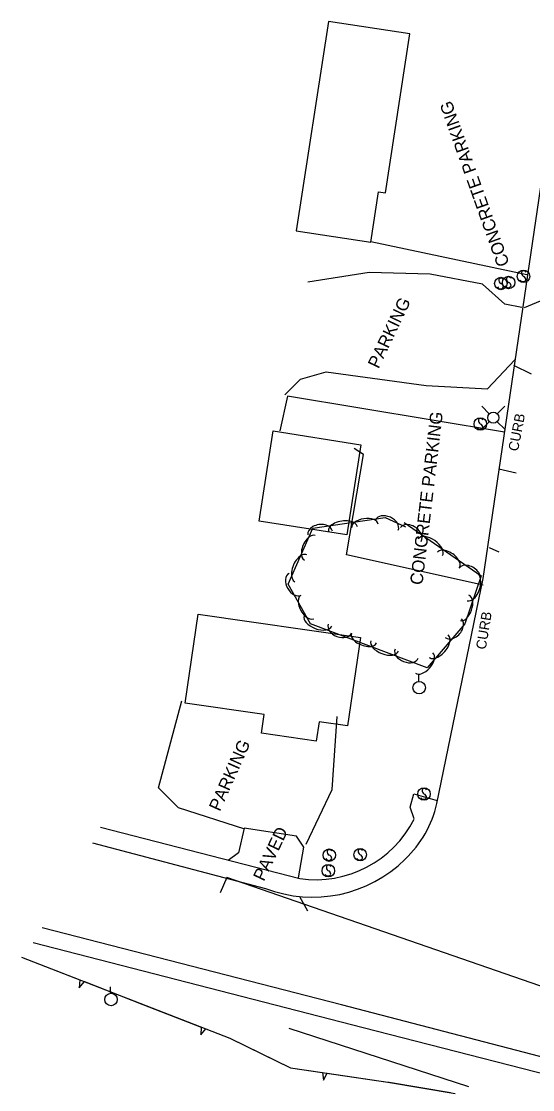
# Model space of a CAD drawing. Extents: x 978516 to 993312, y 1836504 to 1846212.
# Drawn here: x 980035.5 to 980239.3, y 1842344.4 to 1842770.2 of the extents above; entities that cross this region are included whole.
import ezdxf

# ---------------------------------------------------------------- set-up
doc = ezdxf.new("R2010")
doc.units = 0
for name, color, linetype in [('S_BUILDING', 7, 'Continuous'), ('S_CURB', 7, 'Continuous'), ('S_CURB_ANNOT', 7, 'Continuous'), ('S_EDGE_PAVEMENT', 7, 'Continuous'), ('S_PARKING', 7, 'Continuous'), ('S_PARKING_ANNOT', 7, 'Continuous'), ('S_SIDEWALK', 7, 'Continuous'), ('S_SIGN', 7, 'Continuous'), ('S_STREAM', 7, 'Continuous'), ('S_TREE', 7, 'Continuous'), ('S_UTILITY_POLE', 7, 'Continuous')]:
    doc.layers.add(name, color=color, linetype=linetype)

msp = doc.modelspace()

# ---------------------------------------------------------------- linework, layer by layer
at = {"layer": 'S_BUILDING'}
for points in [[(980157.9, 1842770.23), (980145.1, 1842686.75), (980174.82, 1842682.19), (980177.9, 1842702.26), (980180.61, 1842701.85), (980190.33, 1842765.26)], [(980130.27, 1842571.05), (980135.91, 1842606.96), (980170.84, 1842601.47), (980165.19, 1842565.57)], [(980105.96, 1842533.92), (980170.64, 1842524.55), (980165.53, 1842489.34), (980154.17, 1842490.99), (980153.05, 1842483.26), (980131.18, 1842486.43), (980132.26, 1842493.89), (980100.81, 1842498.45)]]:
    msp.add_lwpolyline(points, close=True, dxfattribs=at)
at = {"layer": 'S_CURB'}
for points in [[(980236.03, 1842656.21), (980242.46, 1842658.84)], [(980231.73, 1842633.13), (980238.8, 1842629.75)], [(980225.8, 1842591.86), (980232.71, 1842590.21)], [(980221.96, 1842560.49), (980225.89, 1842558.8)], [(980451.78, 1842317.97), (980454.14, 1842322.92), (980406.74, 1842323.37), (980408.92, 1842328.13), (980117.46, 1842428.99), (980114.74, 1842422.8)], [(980146.34, 1842421.39), (980149.6, 1842415.68)]]:
    msp.add_lwpolyline(points, dxfattribs=at)
at = {"layer": 'S_EDGE_PAVEMENT'}
for points in [[(980201.17, 1842458.38), (980219.61, 1842548.19), (980247.02, 1842734.04)], [(980063.86, 1842442.82), (980132.8, 1842424.58)], [(980258.08, 1842353.43), (980163.15, 1842378.14), (980043.71, 1842408.83)]]:
    msp.add_lwpolyline(points, dxfattribs=at)
for centre, major_axis, ratio, start_param, end_param in [((980300.02, 1842452.04), (20.47, -53.98), 0.993262, 4.118369, 5.635545), ((980158.21, 1842468.18), (43.05, -9.37), 0.999483, 5.686714, 6.273325), ((980151.52, 1842473.83), (35.98, -38.6), 0.998092, 5.16884, 6.311252)]:
    msp.add_ellipse(centre, major_axis=major_axis, ratio=ratio, start_param=start_param, end_param=end_param, dxfattribs=at)
at = {"layer": 'S_PARKING'}
for points in [[(980237.07, 1842669.22), (980174.81, 1842682.4)], [(980235.09, 1842656.2), (980228.25, 1842657.51), (980219.34, 1842665.45), (980198.52, 1842669.42), (980174.14, 1842670.14), (980149.75, 1842666.22)], [(980140.57, 1842621.38), (980146.74, 1842627.61), (980156.96, 1842630.52), (980196.85, 1842625.09), (980221.38, 1842623.76), (980232.2, 1842635.35)], [(980228.12, 1842606.46), (980141.56, 1842620.77), (980138.53, 1842606.97)], [(980219.56, 1842545.42), (980165.11, 1842557.6), (980171.84, 1842597.6), (980168.21, 1842600.02)], [(980124.58, 1842448.2), (980098.08, 1842456.66), (980090.14, 1842464.64), (980099.44, 1842499.37)], [(980148.97, 1842442.27), (980159.36, 1842464.07), (980161.42, 1842493.15)], [(980145.92, 1842428.84), (980148.06, 1842440.97), (980145.14, 1842445.44), (980124.27, 1842448.67), (980122.01, 1842438.83), (980117.91, 1842435.75)]]:
    msp.add_lwpolyline(points, dxfattribs=at)
at = {"layer": 'S_SIDEWALK'}
for points in [[(980192.11, 1842452.26), (980190.52, 1842457.02), (980192.03, 1842462.29), (980201.21, 1842459.58)], [(980066.97, 1842449.01), (980146.52, 1842428.48)], [(980040.13, 1842403.02), (980171.77, 1842369.1), (980272.43, 1842343.3), (980306.44, 1842334.58)]]:
    msp.add_lwpolyline(points, dxfattribs=at)
msp.add_ellipse((980152.58, 1842472.25), major_axis=(38.39, -22.11), ratio=0.997054, start_param=5.096353, end_param=6.337566, dxfattribs=at)
at = {"layer": 'S_SIGN'}
for centre in [(980235.67, 1842668.57), (980226.67, 1842665.71), (980229.75, 1842666.15), (980218.51, 1842609.7), (980196.05, 1842462.2), (980158.24, 1842437.85), (980170.55, 1842438.01), (980157.88, 1842431.64)]:
    msp.add_circle(centre, 2.49, dxfattribs=at)
for centre, radius, start, end in [((980236.35, 1842669.9), 1.5, 167.1196, 241.9813), ((980235.74, 1842669.84), 0.95, 16.5258, 156.8957), ((980227.36, 1842667.03), 1.5, 167.1196, 241.9813), ((980226.75, 1842666.97), 0.95, 16.5258, 156.8957), ((980226.26, 1842664.36), 1.4, 358.6529, 73.7063), ((980229.6, 1842665.32), 1.28, 204.641, 335.359), ((980230.44, 1842667.47), 1.5, 167.1196, 241.9813), ((980229.83, 1842667.41), 0.95, 16.5258, 156.8957), ((980229.34, 1842664.8), 1.4, 358.6529, 73.7063), ((980235.51, 1842667.75), 1.28, 204.641, 335.359), ((980235.25, 1842667.23), 1.4, 358.6529, 73.7063), ((980226.52, 1842664.88), 1.28, 204.641, 335.359), ((980219.19, 1842611.03), 1.5, 167.1196, 241.9813), ((980218.58, 1842610.97), 0.95, 16.5258, 156.8957), ((980218.09, 1842608.36), 1.4, 358.6529, 73.7063), ((980218.35, 1842608.88), 1.28, 204.641, 335.359), ((980196.13, 1842463.47), 0.95, 16.5258, 156.8957), ((980195.9, 1842461.38), 1.28, 204.641, 335.359), ((980196.74, 1842463.53), 1.5, 167.1196, 241.9813), ((980195.64, 1842460.86), 1.4, 358.6529, 73.7063), ((980158.92, 1842439.17), 1.5, 167.1196, 241.9813), ((980158.31, 1842439.11), 0.95, 16.5258, 156.8957), ((980171.23, 1842439.34), 1.5, 167.1196, 241.9813), ((980170.62, 1842439.28), 0.95, 16.5258, 156.8957), ((980158.08, 1842437.02), 1.28, 204.641, 335.359), ((980157.82, 1842436.5), 1.4, 358.6529, 73.7063), ((980170.39, 1842437.19), 1.28, 204.641, 335.359), ((980170.13, 1842436.67), 1.4, 358.6529, 73.7063), ((980158.57, 1842432.97), 1.5, 167.1196, 241.9813), ((980157.96, 1842432.91), 0.95, 16.5258, 156.8957), ((980157.47, 1842430.3), 1.4, 358.6529, 73.7063), ((980157.73, 1842430.82), 1.28, 204.641, 335.359)]:
    msp.add_arc(centre, radius, start, end, dxfattribs=at)
at = {"layer": 'S_STREAM'}
msp.add_lwpolyline([(980213.88, 1842345.54), (980142.2, 1842368.75)], dxfattribs=at)
at = {"layer": 'S_TREE'}
for p, q in [((980058.78, 1842388.13), (980058.57, 1842385)), ((980058.57, 1842385), (980060.61, 1842387.42)), ((980107.21, 1842369.29), (980107, 1842366.16)), ((980107, 1842366.16), (980109.04, 1842368.58)), ((980155.5, 1842351.25), (980156, 1842348.15)), ((980156, 1842348.15), (980157.44, 1842350.97))]:
    msp.add_line(p, q, dxfattribs=at)
for points in [[(980188.07, 1842570.43), (980218.77, 1842549.13), (980212.34, 1842530.1), (980197.3, 1842512.55), (980150.75, 1842530.09), (980141.85, 1842545.92), (980151.64, 1842568.22), (980180.48, 1842572.39), (980188.61, 1842568.74)], [(980035.48, 1842397.2), (980058.78, 1842388.13)], [(980035.48, 1842397.2), (980118.6, 1842364.87), (980142.81, 1842353.13), (980181.61, 1842347.39), (980208.47, 1842342.87)], [(980060.61, 1842387.42), (980083.91, 1842378.36)], [(980083.91, 1842378.36), (980107.21, 1842369.29)], [(980109.04, 1842368.58), (980118.6, 1842364.87), (980131.87, 1842358.43)], [(980131.87, 1842358.43), (980142.81, 1842353.13), (980155.5, 1842351.25)], [(980157.44, 1842350.97), (980181.61, 1842347.39), (980182.14, 1842347.3)], [(980182.14, 1842347.3), (980206.65, 1842343.17)]]:
    msp.add_lwpolyline(points, dxfattribs=at)
for centre, major_axis, ratio, start_param, end_param in [((980163.69, 1842567.82), (-5.8, -0.84), 0.550795, 3.142683, 6.284276), ((980172.45, 1842569.09), (-5.28, -0.76), 0.541403, 3.142649, 6.284241), ((980181.21, 1842569.45), (-4.52, 2.03), 0.68543, 3.141684, 6.283276), ((980154.58, 1842566.24), (-4.9, -0.7), 0.686201, 3.143381, 6.284974), ((980190.78, 1842565.65), (-4.07, 2.82), 0.685871, 3.141781, 6.283374), ((980150.5, 1842560.34), (-2.15, -4.89), 0.54055, 3.142551, 6.284144), ((980198.53, 1842560.59), (-4.82, 3.34), 0.550529, 3.141708, 6.2833), ((980146.93, 1842552.23), (-2.36, -5.37), 0.549928, 3.142582, 6.284175), ((980205.81, 1842555.54), (-4.39, 3.05), 0.541141, 3.141704, 6.283297), ((980144.63, 1842545.84), (2.42, -4.31), 0.686697, 3.14337, 6.284962), ((980214.12, 1842549.46), (-4.07, 2.82), 0.685871, 3.141781, 6.283374), ((980215.08, 1842544.83), (1.88, 5.56), 0.549683, 3.141862, 6.283455), ((980149.44, 1842536.75), (2.61, -4.65), 0.541793, 3.142641, 6.284234), ((980212.24, 1842536.43), (1.71, 5.06), 0.54031, 3.141854, 6.283446), ((980153.76, 1842531.23), (5.49, -2.07), 0.550273, 3.141461, 6.283053), ((980162.51, 1842528.21), (4.64, -1.75), 0.685551, 3.141377, 6.282969), ((980207.71, 1842528.36), (3.22, 3.76), 0.684817, 3.141155, 6.282748), ((980172.06, 1842524.33), (5, -1.88), 0.540889, 3.141465, 6.283058), ((980201.88, 1842521.16), (3.82, 4.46), 0.549684, 3.141325, 6.282918), ((980180.35, 1842521.21), (5.49, -2.07), 0.550273, 3.141461, 6.283053), ((980189.1, 1842518.19), (4.64, -1.75), 0.685551, 3.141377, 6.282969), ((980196.11, 1842514.43), (3.48, 4.06), 0.54031, 3.141334, 6.282926)]:
    msp.add_ellipse(centre, major_axis=major_axis, ratio=ratio, start_param=start_param, end_param=end_param, dxfattribs=at)
at = {"layer": 'S_UTILITY_POLE'}
for p, q in [((980222.04, 1842613.81), (980219.05, 1842616.79)), ((980225.21, 1842613.81), (980228.2, 1842616.79)), ((980222.04, 1842610.63), (980219.05, 1842607.65)), ((980225.21, 1842610.63), (980228.2, 1842607.65)), ((980193.94, 1842507.11), (980193.94, 1842509.59)), ((980071.08, 1842382.83), (980071.08, 1842385.31))]:
    msp.add_line(p, q, dxfattribs=at)
for centre, radius in [((980223.63, 1842612.23), 2.21), ((980194.08, 1842504.59), 2.5), ((980071.22, 1842380.31), 2.5)]:
    msp.add_circle(centre, radius, dxfattribs=at)

# ---------------------------------------------------------------- texts
at = {"layer": 'S_CURB_ANNOT'}
for rotation, p in [(79.1365, (980233.5, 1842598.64)), (80.754, (980220.64, 1842519.63))]:
    msp.add_text('CURB', height=4, rotation=rotation, dxfattribs=at).set_placement(p)
at = {"layer": 'S_PARKING_ANNOT'}
for s, height, rotation, p in [('CONCRETE PARKING', 5.0005, 109.6153, (980230.19, 1842673.53)), ('PARKING', 5, 64.4882, (980177.9, 1842631.49)), ('CONCRETE PARKING', 5.0005, 83.2179, (980195.37, 1842545.37)), ('PARKING', 5, 65.8995, (980114.63, 1842454.99)), ('PAVED', 5, 64.4882, (980132.17, 1842427.12))]:
    msp.add_text(s, height=height, rotation=rotation, dxfattribs=at).set_placement(p)

doc.saveas('drawing.dxf')
